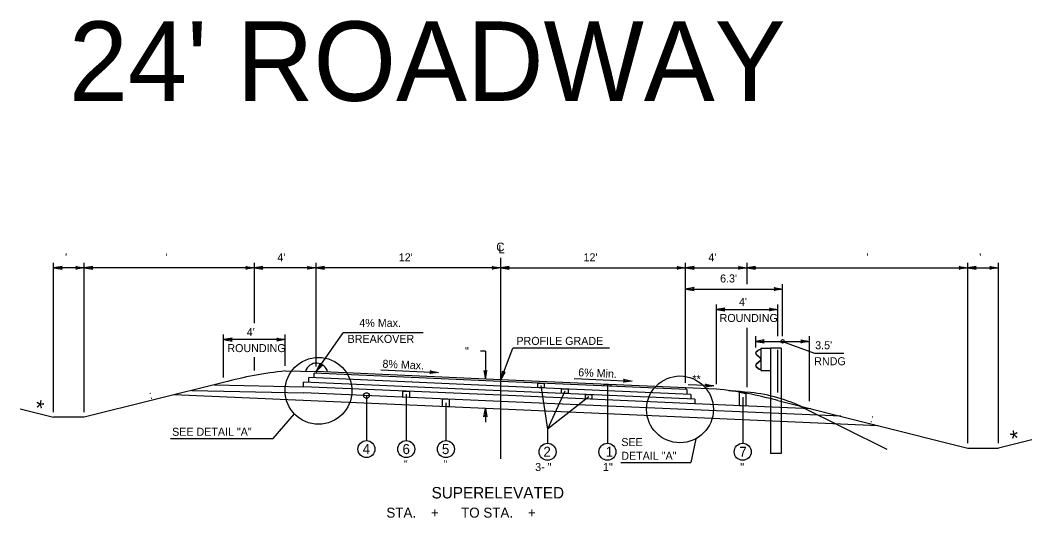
# Model space of a CAD drawing. Extents: x -540 to 1231, y -564 to 421.
# Drawn here: x 1038.3 to 1215.3, y -125.1 to -38.1 of the extents above; entities that cross this region are included whole.
import ezdxf

# ---------------------------------------------------------------- set-up
doc = ezdxf.new("R2010")
doc.units = 0
doc.layers.add('1', color=7, linetype='Continuous')
doc.layers.add('Des_ Drain_ Ftrs', color=7, linetype='Continuous')

msp = doc.modelspace()

# ---------------------------------------------------------------- linework, layer by layer
at = {"layer": '1'}
for p, q in [((1122.38, -114.8), (1122.38, -79.62)), ((1044.11, -106.64), (1044.11, -80.5)), ((1049.5, -81.38), (1044.11, -81.38)), ((1049.5, -106.64), (1049.5, -80.5)), ((1079.27, -81.38), (1049.5, -81.38)), ((1079.27, -91.06), (1079.27, -80.5)), ((1090.05, -81.38), (1079.27, -81.38)), ((1090.05, -98.65), (1090.05, -80.5)), ((1122.38, -81.38), (1090.05, -81.38)), ((1122.38, -81.38), (1154.71, -81.38)), ((1154.71, -101.47), (1154.71, -80.5)), ((1154.71, -81.38), (1165.48, -81.38)), ((1165.48, -84.2), (1165.48, -80.5)), ((1165.48, -81.38), (1204.07, -81.38)), ((1204.07, -112.02), (1204.07, -80.5)), ((1204.07, -81.38), (1209.46, -81.38)), ((1209.46, -112.02), (1209.46, -80.5)), ((1171.68, -93.35), (1171.68, -84.2)), ((1154.71, -85.08), (1171.68, -85.08)), ((1160.09, -101.71), (1160.09, -87.77)), ((1170.87, -93.35), (1170.87, -87.77)), ((1160.09, -88.65), (1170.87, -88.65)), ((1165.48, -102.26), (1165.48, -91.84)), ((1073.88, -100.54), (1073.88, -93.05)), ((1084.66, -98.53), (1084.66, -93.05)), ((1090.04, -99.53), (1094.82, -92.73)), ((1108.77, -92.73), (1094.82, -92.73)), ((1166.99, -95.31), (1166.99, -93.35)), ((1176.37, -104.71), (1176.37, -93.35)), ((1084.66, -93.93), (1073.88, -93.93)), ((1122.38, -100.94), (1124.5, -95.44)), ((1141.41, -95.44), (1124.5, -95.44)), ((1166.99, -94.23), (1176.37, -94.23)), ((1167.9, -95.42), (1167.9, -99.35)), ((1167.9, -95.42), (1169.58, -95.42)), ((1169.58, -95.42), (1169.58, -113.82)), ((1171.41, -95.42), (1169.58, -95.42)), ((1171.41, -95.42), (1171.41, -113.82)), ((1171.68, -94.23), (1177.24, -96.31)), ((1079.27, -99.31), (1079.27, -96.99)), ((1119.68, -95.94), (1118.8, -95.94)), ((1119.68, -95.94), (1119.68, -100.82)), ((1167.05, -96.52), (1167.78, -97.16)), ((1167.58, -95.7), (1167.07, -96.09)), ((1167.07, -96.5), (1167.8, -97.14)), ((1167.6, -95.73), (1167.08, -96.12)), ((1167.9, -95.65), (1167.58, -95.7)), ((1167.9, -95.68), (1167.6, -95.73)), ((1167.87, -97.35), (1167.87, -97.42)), ((1167.9, -97.35), (1167.9, -97.42)), ((1170.87, -103.19), (1170.87, -95.73)), ((1177.24, -96.31), (1182.39, -96.31)), ((1167.78, -97.61), (1167.05, -98.24)), ((1167.8, -97.63), (1167.07, -98.27)), ((1167.07, -98.68), (1167.58, -99.07)), ((1167.08, -98.65), (1167.6, -99.04)), ((1167.58, -99.07), (1167.9, -99.12)), ((1167.6, -99.04), (1167.9, -99.09)), ((1084.66, -99.41), (1090.04, -99.53)), ((1122.38, -102.05), (1088.78, -100.58)), ((1088.78, -101.39), (1088.78, -100.58)), ((1122.38, -101.24), (1089.7, -99.81)), ((1089.7, -100.62), (1089.7, -99.81)), ((1122.38, -100.94), (1090.04, -99.53)), ((1090.04, -99.53), (1090.04, -99.83)), ((1101.36, -99.24), (1111.47, -99.68)), ((1135.23, -100.73), (1145.34, -101.17)), ((1167.9, -99.35), (1169.58, -99.35)), ((1073.88, -101.42), (1049.5, -107.52)), ((1072.29, -101.82), (1087.86, -102.16)), ((1122.38, -102.86), (1087.86, -101.35)), ((1087.86, -102.16), (1087.86, -101.35)), ((1122.38, -103.67), (1087.86, -102.16)), ((1154.71, -102.35), (1122.38, -100.94)), ((1154.95, -102.66), (1122.38, -101.24)), ((1155.65, -103.5), (1122.38, -102.05)), ((1129.4, -101.95), (1130.56, -109.58)), ((1141.03, -101.92), (1141.03, -112.06)), ((1160.09, -102.59), (1154.71, -102.35)), ((1154.71, -102.35), (1154.71, -102.65)), ((1159.67, -102.03), (1155.18, -101.84)), ((1122.38, -106.09), (1065.18, -103.6)), ((1068.32, -102.81), (1087.86, -103.24)), ((1122.38, -104.75), (1087.86, -103.24)), ((1098.87, -103.72), (1098.87, -111.59)), ((1105.83, -103.48), (1105.83, -111.59)), ((1156.35, -104.34), (1122.38, -102.86)), ((1156.35, -105.15), (1122.38, -103.67)), ((1133.58, -102.94), (1130.56, -109.58)), ((1137.75, -103.95), (1130.56, -109.58)), ((1154.95, -102.66), (1154.95, -103.47)), ((1155.65, -103.5), (1155.65, -104.31)), ((1156.35, -104.34), (1156.35, -105.15)), ((1164.7, -103.98), (1164.7, -112.06)), ((1166.99, -103.37), (1166.99, -103.37)), ((1038.28, -106.06), (1044.11, -107.52)), ((1112.77, -105), (1112.77, -111.59)), ((1119.68, -105.98), (1119.68, -108.34)), ((1154.71, -106.16), (1122.38, -104.75)), ((1188.39, -108.98), (1122.38, -106.09)), ((1181.85, -107.34), (1154.71, -106.16)), ((1176.62, -106.04), (1156.35, -105.15)), ((1170.87, -104.6), (1204.07, -112.9)), ((1174.87, -105.6), (1189.92, -113.12)), ((1049.5, -107.52), (1044.11, -107.52)), ((1082.52, -111.25), (1086.26, -106.93)), ((1130.56, -109.58), (1130.56, -112.06)), ((1064.59, -111.25), (1082.52, -111.25)), ((1156.5, -111.27), (1155.61, -115.45)), ((1215.28, -111.44), (1209.46, -112.9)), ((1204.07, -112.9), (1209.46, -112.9)), ((1171.41, -113.82), (1169.58, -113.82)), ((1143.38, -115.45), (1155.61, -115.45))]:
    msp.add_line(p, q, dxfattribs=at)
for points in [[(1128.83, -101.52), (1129.97, -101.57), (1129.97, -102.38), (1128.83, -102.33)], [(1133, -102.51), (1134.15, -102.56), (1134.15, -103.37), (1133, -103.32)], [(1140.45, -101.73), (1141.6, -101.78), (1141.6, -102.08), (1140.45, -102.03)], [(1105.26, -102.92), (1106.41, -102.97), (1106.41, -104.05), (1105.26, -104)], [(1112.19, -104.3), (1113.34, -104.35), (1113.34, -105.7), (1112.19, -105.65)], [(1137.18, -103.51), (1138.32, -103.56), (1138.32, -104.36), (1137.18, -104.31)], [(1164.13, -103.13), (1165.28, -103.33), (1165.28, -105.54), (1164.13, -105.49)]]:
    msp.add_lwpolyline(points, close=True, dxfattribs=at)
for centre, radius in [((1171.68, -94.23), 0.3), ((1090.47, -102.89), 5.84), ((1153.73, -106.13), 5.84), ((1098.87, -103.72), 0.5), ((1098.87, -113.08), 1.49), ((1105.83, -113.08), 1.49), ((1112.77, -113.08), 1.49), ((1130.56, -113.55), 1.49), ((1141.03, -113.55), 1.49), ((1164.7, -113.55), 1.49)]:
    msp.add_circle(centre, radius, dxfattribs=at)
for centre, radius, start, end in [((1167.23, -96.31), 0.278, 126.9799, 229.021), ((1167.23, -96.31), 0.249, 126.9799, 229.021), ((1167.62, -97.35), 0.249, 0, 49.0365), ((1167.62, -97.35), 0.278, 0, 49.0365), ((1090.12, -100.04), 2, 12.2852, 163.8708), ((1167.23, -98.46), 0.278, 130.979, 233.0201), ((1167.23, -98.46), 0.249, 130.979, 233.0201), ((1167.62, -97.42), 0.249, 310.9635, 0), ((1167.62, -97.42), 0.278, 310.9635, 0), ((1091.55, -166.25), 67.19, 95.8901, 105.2487), ((1153.21, -169.42), 67.19, 74.7593, 84.1179), ((1154.66, -203.81), 101.24, 83.8633, 85.6775), ((1163.36, -130.43), 27.37, 65.1374, 85.5513)]:
    msp.add_arc(centre, radius, start, end, dxfattribs=at)
at = {"layer": 'Des_ Drain_ Ftrs'}
for points in [[(1044.11, -81.38), (1045.6, -81.62), (1045.3, -81.38), (1045.6, -81.13)], [(1049.5, -81.38), (1048.01, -81.62), (1048.31, -81.38), (1048.01, -81.13)], [(1049.5, -81.38), (1050.99, -81.62), (1050.69, -81.38), (1050.99, -81.13)], [(1079.27, -81.38), (1077.78, -81.62), (1078.08, -81.38), (1077.78, -81.13)], [(1079.27, -81.38), (1080.76, -81.62), (1080.46, -81.38), (1080.76, -81.13)], [(1090.05, -81.38), (1088.56, -81.62), (1088.85, -81.38), (1088.56, -81.13)], [(1090.05, -81.38), (1091.54, -81.62), (1091.24, -81.38), (1091.54, -81.13)], [(1122.38, -81.38), (1120.89, -81.62), (1121.18, -81.38), (1120.89, -81.13)], [(1122.38, -81.38), (1123.86, -81.62), (1123.57, -81.38), (1123.86, -81.13)], [(1154.71, -81.38), (1153.22, -81.62), (1153.51, -81.38), (1153.22, -81.13)], [(1154.71, -81.38), (1156.19, -81.62), (1155.9, -81.38), (1156.19, -81.13)], [(1165.48, -81.38), (1163.99, -81.62), (1164.29, -81.38), (1163.99, -81.13)], [(1165.48, -81.38), (1166.97, -81.62), (1166.68, -81.38), (1166.97, -81.13)], [(1204.07, -81.38), (1202.58, -81.62), (1202.88, -81.38), (1202.58, -81.13)], [(1204.07, -81.38), (1205.56, -81.62), (1205.26, -81.38), (1205.56, -81.13)], [(1209.46, -81.38), (1207.97, -81.62), (1208.26, -81.38), (1207.97, -81.13)], [(1154.71, -85.08), (1156.19, -85.33), (1155.9, -85.08), (1156.19, -84.83)], [(1171.68, -85.08), (1170.19, -85.33), (1170.48, -85.08), (1170.19, -84.83)], [(1160.09, -88.65), (1161.58, -88.9), (1161.29, -88.65), (1161.58, -88.4)], [(1170.87, -88.65), (1169.38, -88.9), (1169.68, -88.65), (1169.38, -88.4)], [(1073.88, -93.93), (1075.37, -94.17), (1075.08, -93.93), (1075.37, -93.68)], [(1084.66, -93.93), (1083.17, -94.17), (1083.47, -93.93), (1083.17, -93.68)], [(1166.99, -94.23), (1168.47, -94.48), (1168.18, -94.23), (1168.47, -93.99)], [(1176.37, -94.23), (1174.88, -94.48), (1175.18, -94.23), (1174.88, -93.99)], [(1090.04, -99.53), (1091.1, -98.45), (1090.73, -98.55), (1090.69, -98.17)], [(1111.47, -99.68), (1109.97, -99.87), (1110.28, -99.63), (1109.99, -99.37)], [(1119.68, -100.82), (1119.93, -99.33), (1119.68, -99.63), (1119.43, -99.33)], [(1122.38, -100.94), (1123.14, -99.64), (1122.8, -99.83), (1122.68, -99.46)], [(1145.34, -101.17), (1143.85, -101.35), (1144.15, -101.12), (1143.87, -100.86)], [(1159.67, -102.03), (1158.18, -102.22), (1158.48, -101.98), (1158.2, -101.72)], [(1119.68, -105.98), (1119.93, -107.46), (1119.68, -107.17), (1119.43, -107.46)]]:
    msp.add_lwpolyline(points, close=True, dxfattribs=at)

# ---------------------------------------------------------------- texts
at = {"layer": '1'}
for s, height, p in [("24' ROADWAY", 13.8979, (1046.79, -52.16)), (" '", 1.4, (1045.61, -80.23)), ("  '", 1.4, (1062.69, -80.23)), ("4'", 1.4, (1083.27, -80.23)), ("12'", 1.4, (1104.52, -80.23)), ("12'", 1.4, (1136.85, -80.23)), ("4'", 1.4, (1158.7, -80.23)), ("  '", 1.4, (1185.34, -80.23)), (" '", 1.4, (1205.57, -80.23)), ("6.3'", 1.4, (1160.75, -83.93)), ("4'", 1.4, (1164.05, -88.04)), ('ROUNDING', 1.4, (1160.66, -90.84)), ("4'", 1.4, (1077.92, -93.31)), ('4% Max.', 1.4, (1097.62, -91.7)), ('BREAKOVER', 1.4, (1095.57, -94.5)), ('PROFILE GRADE', 1.4, (1125.11, -94.85)), ('ROUNDING', 1.4, (1074.53, -96.11)), ("3.5'", 1.4, (1177.39, -95.61)), ('RNDG', 1.4, (1177.22, -98.41)), ('SEE DETAIL "A"', 1.4, (1064.86, -110.75)), ('SEE', 1.4, (1143.46, -112.55)), ('4', 1.75, (1098.19, -113.95)), ('6', 1.75, (1105.17, -113.95)), ('5', 1.75, (1112.07, -113.95)), ('2', 1.75, (1129.82, -114.42)), ('1', 1.75, (1140.72, -114.42)), ('7', 1.75, (1164.11, -114.42)), (' "', 1.4, (1104.89, -116.44)), (' "', 1.4, (1111.82, -116.44)), ('DETAIL "A"', 1.4, (1143.46, -114.95)), ('3- "', 1.4, (1128.39, -116.91)), ('1"', 1.4, (1140.26, -116.91)), (' "', 1.4, (1163.76, -116.91)), ('SUPERELEVATED', 2, (1110.26, -121.71)), ('STA.    +      TO STA.    +     ', 1.75, (1102.35, -125.07))]:
    msp.add_text(s, height=height, dxfattribs=at).set_placement(p)
for s, height, rotation, p in [('  "', 1.4, 0.1438, (1115.07, -96.65)), ('8% Max.', 1.4, 357.3763, (1101.64, -98.83)), ('6% Min.', 1.4, 357.373, (1135.9, -100.33)), ('**', 1.4, 357.2161, (1155.86, -101.47)), (' : ', 1.4, 14.2282, (1060.51, -104.48)), ('*', 2.8, 347.1521, (1040.6, -107.09)), (' : ', 1.4, 345.7718, (1186.42, -108.2)), ('*', 2.8, 12.8479, (1211.92, -112.71))]:
    msp.add_text(s, height=height, rotation=rotation, dxfattribs=at).set_placement(p)
at = {"layer": 'Des_ Drain_ Ftrs'}
for s, p in [('C', (1121.58, -78.46)), ('L', (1121.97, -78.85))]:
    msp.add_text(s, height=1.5, dxfattribs=at).set_placement(p)

doc.saveas('drawing.dxf')
